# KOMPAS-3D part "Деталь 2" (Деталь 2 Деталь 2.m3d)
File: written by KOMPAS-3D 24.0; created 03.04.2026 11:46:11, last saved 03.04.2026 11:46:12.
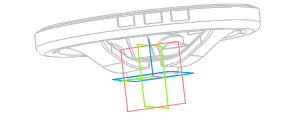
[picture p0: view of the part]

Document properties: Автор: R2D2; Полное имя файла: E:\Работа\Зайцев\Аксессуары для пневмоприводов\Ручной дублер DN.ru\MON1-250-T26-ISO Ручной дублер DN.ru\исходные материалы\Деталь 2 Деталь 2.m3d

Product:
- Body: Твердое тело1  | qty 1
    Масса: 1.734021
- Part/product: Деталь 2
    Масса: 1.734021
    additional columns: Типовые

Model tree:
1. Твердое тело1  (labels: Твердое тело1)
2. Масштабирование:1
3. Масштабирование : Твердое тело1
     Масштаб по оси Х = 1; Масштаб по оси Y = 1; Масштаб по оси Z = 1; Коэффициент = 1.166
